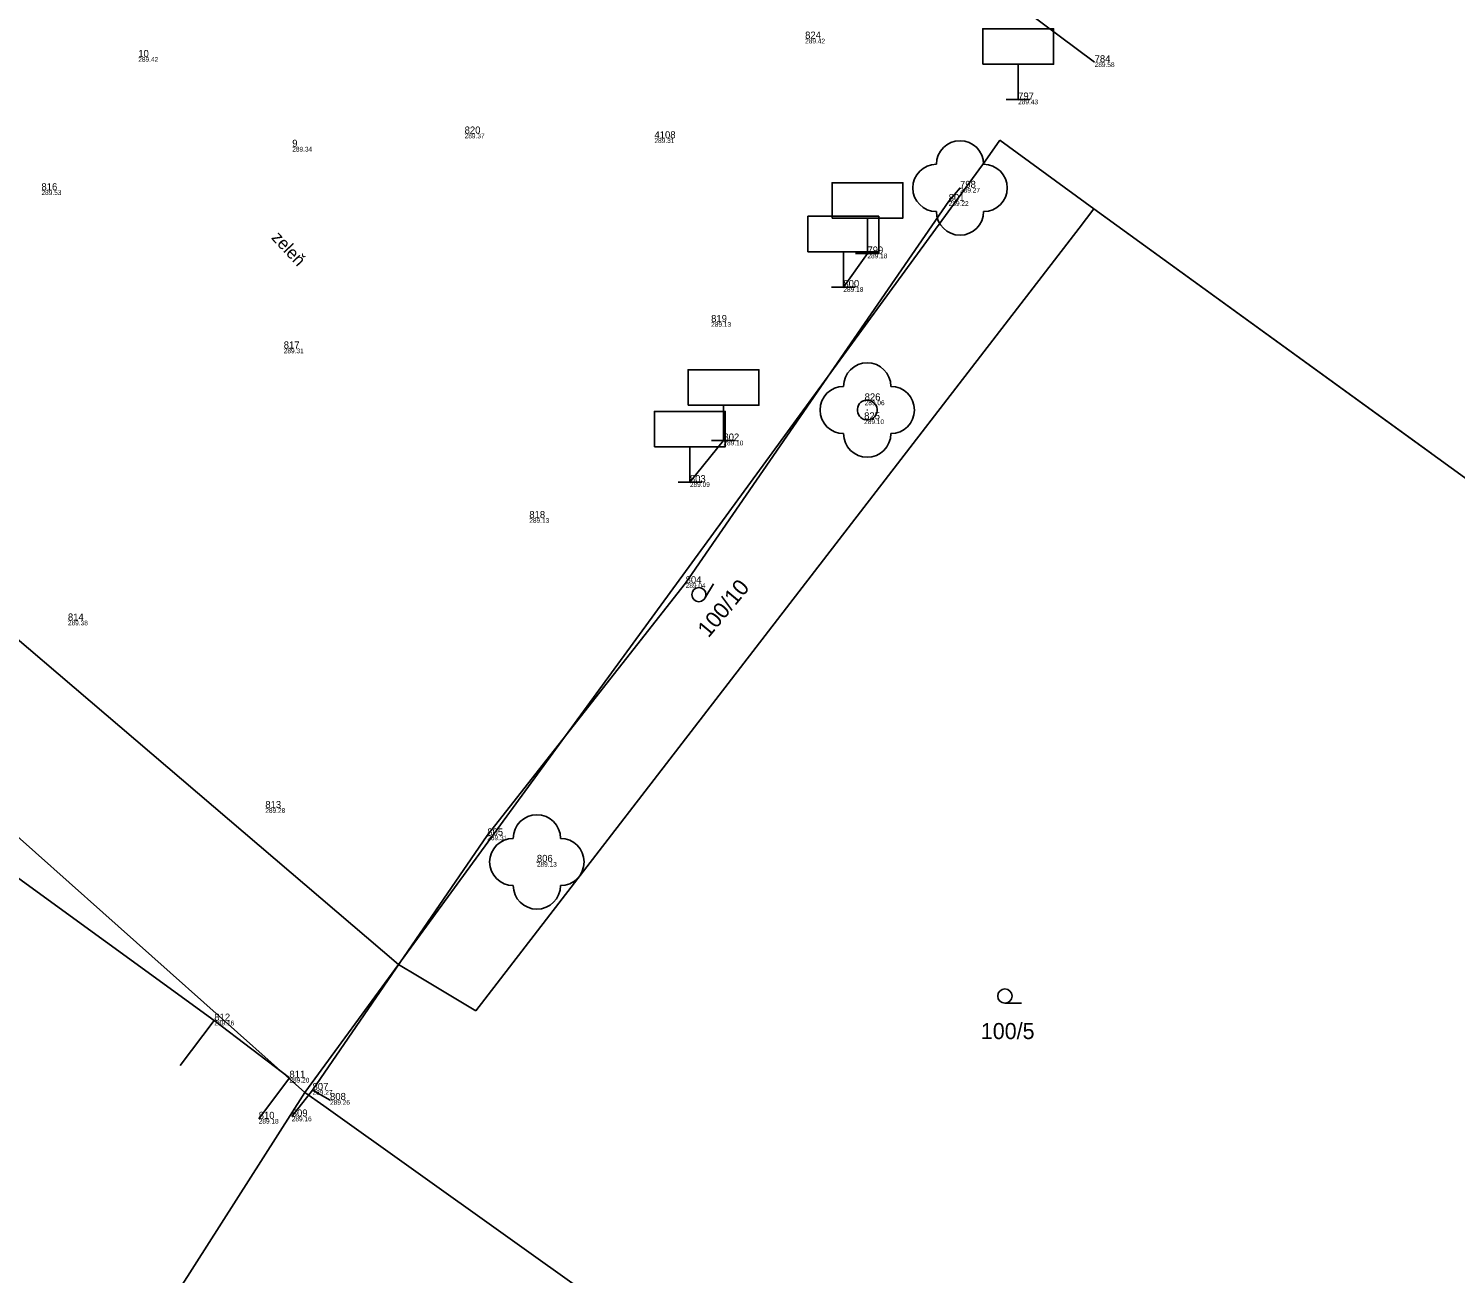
# Model space of a CAD drawing. Extents: x -805057 to -804930, y -994399 to -994240.
# Drawn here: x -804980.6 to -804950.39, y -994368.95 to -994342.6 of the extents above; entities that cross this region are included whole.
import ezdxf

# ---------------------------------------------------------------- set-up
doc = ezdxf.new("R2010")
doc.units = 0
for name, color, linetype in [('bod cislo', 7, 'Continuous'), ('bod pozice', 7, 'Continuous'), ('bod výška', 7, 'Continuous'), ('Katastralni mapa', 7, 'Continuous'), ('komunikace', 7, 'Continuous'), ('plot', 7, 'Continuous'), ('popis', 7, 'Continuous'), ('strom', 7, 'Continuous'), ('svah', 7, 'Continuous'), ('značka', 7, 'Continuous')]:
    doc.layers.add(name, color=color, linetype=linetype)

msp = doc.modelspace()

# ---------------------------------------------------------------- linework, layer by layer
at = {"layer": 'bod pozice'}
for p, q in [((-804964.16, -994342.81), (-804964.16, -994342.81)), ((-804978.28, -994343.2), (-804978.28, -994343.2)), ((-804958.03, -994343.31), (-804958.03, -994343.31)), ((-804959.65, -994344.1), (-804959.65, -994344.1)), ((-804975.02, -994345.1), (-804975.02, -994345.1)), ((-804971.37, -994344.82), (-804971.37, -994344.82)), ((-804967.35, -994344.92), (-804967.35, -994344.92)), ((-804980.33, -994346.02), (-804980.33, -994346.02)), ((-804960.88, -994345.97), (-804960.88, -994345.97)), ((-804961.12, -994346.25), (-804961.12, -994346.25)), ((-804962.84, -994347.36), (-804962.84, -994347.36)), ((-804963.35, -994348.07), (-804963.35, -994348.07)), ((-804966.15, -994348.81), (-804966.15, -994348.81)), ((-804975.2, -994349.37), (-804975.2, -994349.37)), ((-804962.9, -994350.47), (-804962.9, -994350.47)), ((-804962.91, -994350.87), (-804962.91, -994350.87)), ((-804965.89, -994351.32), (-804965.89, -994351.32)), ((-804966.6, -994352.2), (-804966.6, -994352.2)), ((-804970, -994352.96), (-804970, -994352.96)), ((-804966.69, -994354.34), (-804966.69, -994354.34)), ((-804979.77, -994355.13), (-804979.77, -994355.13)), ((-804975.59, -994359.1), (-804975.59, -994359.1)), ((-804970.89, -994359.68), (-804970.89, -994359.68)), ((-804969.84, -994360.24), (-804969.84, -994360.24)), ((-804976.67, -994363.6), (-804976.67, -994363.6)), ((-804975.08, -994364.81), (-804975.08, -994364.81)), ((-804974.59, -994365.07), (-804974.59, -994365.07)), ((-804974.22, -994365.28), (-804974.22, -994365.28)), ((-804975.03, -994365.63), (-804975.03, -994365.63)), ((-804975.73, -994365.68), (-804975.73, -994365.68))]:
    msp.add_line(p, q, dxfattribs=at)
at = {"layer": 'Katastralni mapa'}
msp.add_line((-804958.05, -994346.41), (-804939.13, -994360.125), dxfattribs=at)
for points in [[(-804960.04, -994344.96), (-804960.35, -994345.4)], [(-804960.04, -994344.96), (-804958.05, -994346.41)], [(-804960.35, -994345.4), (-804972.77, -994362.41)], [(-804958.36, -994346.82), (-804958.05, -994346.41)], [(-804958.05, -994346.41), (-804950.9, -994351.593)], [(-804971.13, -994363.39), (-804958.36, -994346.82)], [(-804972.77, -994362.41), (-804987.82, -994349.57)], [(-804974.75, -994365.12), (-804991.87, -994349.88)], [(-804966.281, -994354.656), (-804966.103, -994354.354)], [(-804972.77, -994362.41), (-804974.75, -994365.12)], [(-804972.77, -994362.41), (-804972.37, -994362.65)], [(-804972.37, -994362.65), (-804971.13, -994363.39)], [(-804959.93, -994363.23), (-804959.579, -994363.23)], [(-804977.97, -994370.17), (-804974.75, -994365.12)], [(-804974.75, -994365.12), (-804974.35, -994365.4)], [(-804974.35, -994365.4), (-804964.81, -994372.21)]]:
    msp.add_lwpolyline(points, dxfattribs=at)
for centre, radius in [((-804966.41, -994354.58), 0.15), ((-804959.93, -994363.079), 0.151)]:
    msp.add_circle(centre, radius, dxfattribs=at)
at = {"layer": 'komunikace'}
for p, q in [((-804966.84, -994336.73), (-804958.03, -994343.31)), ((-804976.67, -994363.6), (-804977.39, -994364.546)), ((-804975.08, -994364.81), (-804976.67, -994363.6)), ((-804975.73, -994365.68), (-804975.08, -994364.81))]:
    msp.add_line(p, q, dxfattribs=at)
at = {"layer": 'plot'}
for p, q in [((-804976.67, -994363.6), (-804984.98, -994357.56)), ((-804974.59, -994365.07), (-804975.03, -994365.63)), ((-804974.22, -994365.28), (-804974.59, -994365.07))]:
    msp.add_line(p, q, dxfattribs=at)
at = {"layer": 'strom'}
for p, q in [((-804961.12, -994346.25), (-804960.88, -994345.97)), ((-804966.69, -994354.34), (-804961.12, -994346.25))]:
    msp.add_line(p, q, dxfattribs=at)
for centre in [(-804960.88, -994345.97), (-804962.845, -994350.672), (-804969.84, -994360.24)]:
    msp.add_circle(centre, 0.0005, dxfattribs=at)
for centre, start, end in [((-804960.88, -994345.47), 0, 180), ((-804961.38, -994345.97), 90, 270), ((-804960.38, -994345.97), 270, 90), ((-804960.88, -994346.47), 180, 360), ((-804962.845, -994350.172), 0, 180), ((-804963.345, -994350.672), 90, 270), ((-804962.345, -994350.672), 270, 90), ((-804962.845, -994351.172), 180, 360), ((-804969.84, -994359.74), 0, 180), ((-804970.34, -994360.24), 90, 270), ((-804969.34, -994360.24), 270, 90), ((-804969.84, -994360.74), 180, 360)]:
    msp.add_arc(centre, 0.5, start, end, dxfattribs=at)
msp.add_ellipse((-804962.845, -994350.672), major_axis=(-0.201, 0.062), ratio=0.994656, dxfattribs=at)
at = {"layer": 'svah'}
for p, q in [((-804970.89, -994359.68), (-804966.69, -994354.34)), ((-804974.59, -994365.07), (-804970.89, -994359.68))]:
    msp.add_line(p, q, dxfattribs=at)
at = {"layer": 'značka'}
for p, q in [((-804959.65, -994343.35), (-804959.65, -994344.1)), ((-804959.9, -994344.1), (-804959.4, -994344.1)), ((-804962.84, -994346.61), (-804962.84, -994347.36)), ((-804963.35, -994347.32), (-804963.35, -994348.07)), ((-804963.35, -994348.07), (-804962.84, -994347.36)), ((-804963.09, -994347.36), (-804962.59, -994347.36)), ((-804963.6, -994348.07), (-804963.1, -994348.07)), ((-804965.89, -994350.57), (-804965.89, -994351.32)), ((-804966.6, -994352.2), (-804965.89, -994351.32)), ((-804966.6, -994351.45), (-804966.6, -994352.2)), ((-804966.14, -994351.32), (-804965.64, -994351.32)), ((-804966.85, -994352.2), (-804966.35, -994352.2))]:
    msp.add_line(p, q, dxfattribs=at)
for points in [[(-804960.4, -994343.35), (-804958.9, -994343.35), (-804958.9, -994342.6), (-804960.4, -994342.6)], [(-804963.59, -994346.61), (-804962.09, -994346.61), (-804962.09, -994345.86), (-804963.59, -994345.86)], [(-804964.1, -994347.32), (-804962.6, -994347.32), (-804962.6, -994346.57), (-804964.1, -994346.57)], [(-804966.64, -994350.57), (-804965.14, -994350.57), (-804965.14, -994349.82), (-804966.64, -994349.82)], [(-804967.35, -994351.45), (-804965.85, -994351.45), (-804965.85, -994350.7), (-804967.35, -994350.7)]]:
    msp.add_lwpolyline(points, close=True, dxfattribs=at)

# ---------------------------------------------------------------- texts
at = {"layer": 'bod cislo'}
for s, p in [('824    ', (-804964.16, -994342.81)), ('10    ', (-804978.28, -994343.2)), ('784    ', (-804958.03, -994343.31)), ('797    ', (-804959.65, -994344.1)), ('820    ', (-804971.37, -994344.82)), ('4108    ', (-804967.35, -994344.92)), ('9    ', (-804975.02, -994345.1)), ('816    ', (-804980.33, -994346.02)), ('798    ', (-804960.88, -994345.97)), ('801    ', (-804961.12, -994346.25)), ('799    ', (-804962.84, -994347.36)), ('800    ', (-804963.35, -994348.07)), ('819    ', (-804966.15, -994348.81)), ('817    ', (-804975.2, -994349.37)), ('826    ', (-804962.9, -994350.47)), ('825    ', (-804962.91, -994350.87)), ('802    ', (-804965.89, -994351.32)), ('803    ', (-804966.6, -994352.2)), ('818    ', (-804970, -994352.96)), ('804    ', (-804966.69, -994354.34)), ('814    ', (-804979.77, -994355.13)), ('813    ', (-804975.59, -994359.1)), ('805    ', (-804970.89, -994359.68)), ('806    ', (-804969.84, -994360.24)), ('812    ', (-804976.67, -994363.6)), ('811    ', (-804975.08, -994364.81)), ('807    ', (-804974.59, -994365.07)), ('808    ', (-804974.22, -994365.28)), ('810    ', (-804975.73, -994365.68)), ('809    ', (-804975.03, -994365.63))]:
    msp.add_text(s, height=0.15, dxfattribs=at).set_placement(p)
at = {"layer": 'bod výška'}
for s, p in [('289.42  ', (-804964.16, -994342.91)), ('289.42  ', (-804978.28, -994343.3)), ('289.58  ', (-804958.03, -994343.41)), ('289.43  ', (-804959.65, -994344.2)), ('289.34  ', (-804975.02, -994345.2)), ('289.37  ', (-804971.37, -994344.92)), ('289.31  ', (-804967.35, -994345.02)), ('289.53  ', (-804980.33, -994346.12)), ('289.27  ', (-804960.88, -994346.07)), ('289.22  ', (-804961.12, -994346.35)), ('289.18  ', (-804962.84, -994347.46)), ('289.18  ', (-804963.35, -994348.17)), ('289.13  ', (-804966.15, -994348.91)), ('289.31  ', (-804975.2, -994349.47)), ('289.06  ', (-804962.9, -994350.57)), ('289.10  ', (-804962.91, -994350.97)), ('289.10  ', (-804965.89, -994351.42)), ('289.09  ', (-804966.6, -994352.3)), ('289.13  ', (-804970, -994353.06)), ('289.04  ', (-804966.69, -994354.44)), ('289.38  ', (-804979.77, -994355.23)), ('289.28  ', (-804975.59, -994359.2)), ('289.31  ', (-804970.89, -994359.78)), ('289.13  ', (-804969.84, -994360.34)), ('289.16  ', (-804976.67, -994363.7)), ('289.20  ', (-804975.08, -994364.91)), ('289.27  ', (-804974.59, -994365.17)), ('289.26  ', (-804974.22, -994365.38)), ('289.16  ', (-804975.03, -994365.73)), ('289.18  ', (-804975.73, -994365.78))]:
    msp.add_text(s, height=0.1, dxfattribs=at).set_placement(p)
at = {"layer": 'Katastralni mapa'}
msp.add_text('100/10', height=0.34, rotation=50.4004, dxfattribs=at).set_placement((-804966.206, -994355.509))
msp.add_text('100/5', height=0.34, dxfattribs=at).set_placement((-804960.44, -994363.99))
at = {"layer": 'popis'}
msp.add_text('zeleň', height=0.2629, rotation=313.0307, dxfattribs=at).set_placement((-804975.476, -994347.035))

doc.saveas('drawing.dxf')
